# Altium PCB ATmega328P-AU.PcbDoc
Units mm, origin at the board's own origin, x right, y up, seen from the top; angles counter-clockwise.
Board outline 20.93 x 20.56 mm, 2 copper layers (Top Layer, Bottom Layer); 1 components, 0 nets, 32 pads, 0 vias.
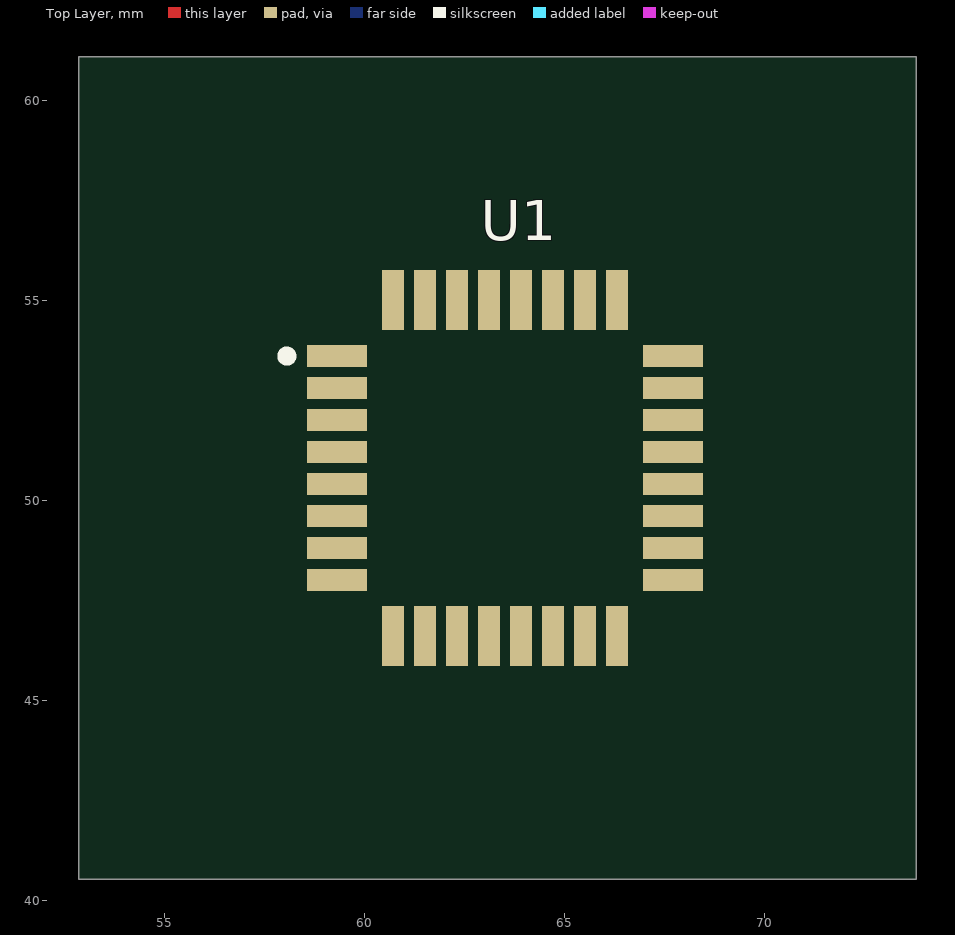
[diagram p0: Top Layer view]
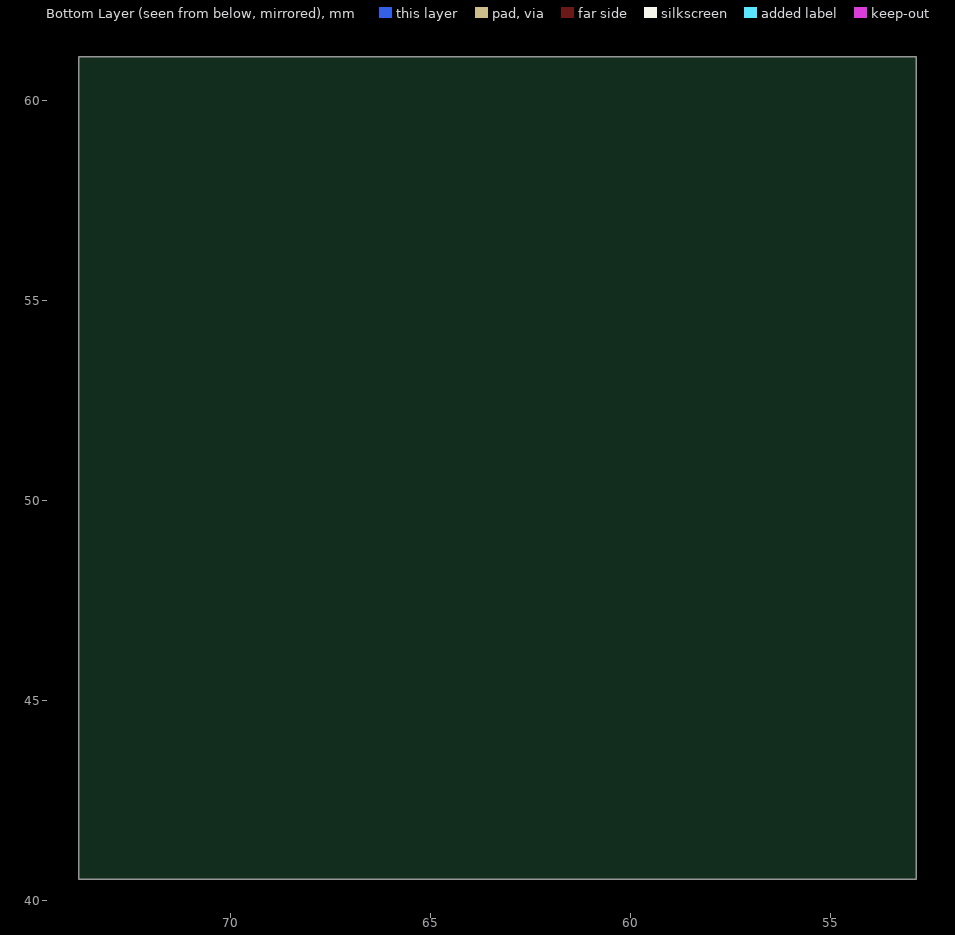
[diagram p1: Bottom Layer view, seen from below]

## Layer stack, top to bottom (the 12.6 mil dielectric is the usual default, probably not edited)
Top Layer: signal copper (thickness not stored)
Dielectric: dielectric 0.32, FR-4, Dk 4.8
Bottom Layer: signal copper (thickness not stored)

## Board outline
52.85,40.52 73.78,40.52 73.78,61.08 52.85,61.08

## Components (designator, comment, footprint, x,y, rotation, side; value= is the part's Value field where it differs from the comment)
U1 "ATmega328P-AU" TQFP-32_7x7mm_P0.8mm 63.5,50.8 r0 top

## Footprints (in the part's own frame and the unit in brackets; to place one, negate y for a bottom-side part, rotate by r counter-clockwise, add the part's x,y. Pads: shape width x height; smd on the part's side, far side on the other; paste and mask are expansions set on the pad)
TQFP-32_7x7mm_P0.8mm [mm]
  rect 1.5x0.55 smd: 1(-4.2,2.8) 2(-4.2,2) 3(-4.2,1.2) 4(-4.2,0.4) 5(-4.2,-0.4) 6(-4.2,-1.2) 7(-4.2,-2) 8(-4.2,-2.8) 17(4.2,-2.8) 18(4.2,-2) 19(4.2,-1.2) 20(4.2,-0.4) 21(4.2,0.4) 22(4.2,1.2) 23(4.2,2) 24(4.2,2.8)
  rect 0.55x1.5 smd: 9(-2.8,-4.2) 10(-2,-4.2) 11(-1.2,-4.2) 12(-0.4,-4.2) 13(0.4,-4.2) 14(1.2,-4.2) 15(2,-4.2) 16(2.8,-4.2) 25(2.8,4.2) 26(2,4.2) 27(1.2,4.2) 28(0.4,4.2) 29(-0.4,4.2) 30(-1.2,4.2) 31(-2,4.2) 32(-2.8,4.2)
  silkscreen extent -5.57,2.68 -5.33,2.92

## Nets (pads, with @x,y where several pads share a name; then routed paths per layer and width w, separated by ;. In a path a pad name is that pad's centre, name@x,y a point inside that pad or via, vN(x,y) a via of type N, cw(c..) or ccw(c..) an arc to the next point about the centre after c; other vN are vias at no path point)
pads on no net: U1.1 U1.2 U1.3 U1.4 U1.5 U1.6 U1.7 U1.8 U1.9 U1.10 U1.11 U1.12 U1.13 U1.14 U1.15 U1.16 U1.17 U1.18 U1.19 U1.20 U1.21 U1.22 U1.23 U1.24 U1.25 U1.26 U1.27 U1.28 U1.29 U1.30 U1.31 U1.32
